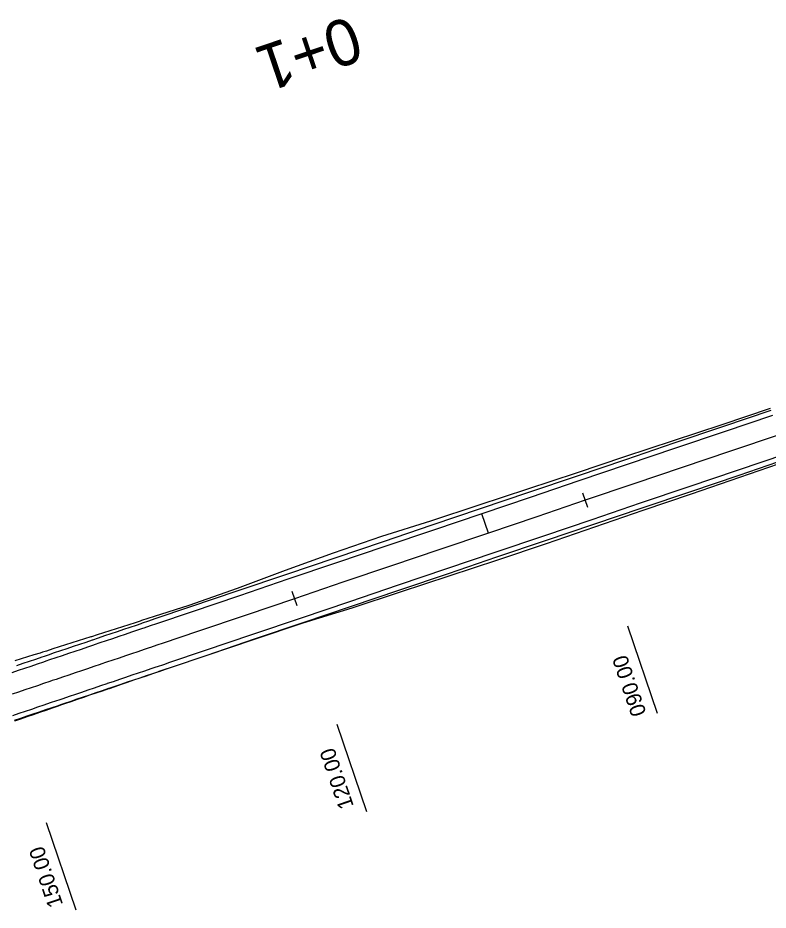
# Model space of a CAD drawing. Extents: x -550605 to -538780, y -1102367 to -1093705.
# Drawn here: x -546596.2 to -546522.8, y -1100741.3 to -1100654.1 of the extents above; entities that cross this region are included whole.
import ezdxf

# ---------------------------------------------------------------- set-up
doc = ezdxf.new("R2010")
doc.units = 0
for name, color, linetype in [('SIT - hrany vozovky', 7, 'Continuous'), ('SIT - osa cesty', 7, 'Continuous'), ('SIT - paty násypů', 7, 'Continuous'), ('SIT - staničení po 100m', 7, 'Continuous'), ('SIT - staničení po 30m', 7, 'Continuous')]:
    doc.layers.add(name, color=color, linetype=linetype)

msp = doc.modelspace()

# ---------------------------------------------------------------- linework, layer by layer
at = {"layer": 'SIT - hrany vozovky'}
for points in [[(-546522.558, -1100692.477), (-546527.294, -1100694.08), (-546532.03, -1100695.684), (-546536.766, -1100697.287), (-546541.502, -1100698.89), (-546546.238, -1100700.494), (-546550.974, -1100702.097), (-546555.709, -1100703.701), (-546560.445, -1100705.304), (-546565.181, -1100706.907), (-546569.917, -1100708.511), (-546574.653, -1100710.114), (-546579.389, -1100711.717), (-546582.768, -1100712.861), (-546583.382, -1100713.069), (-546583.997, -1100713.277), (-546584.125, -1100713.321), (-546584.611, -1100713.485), (-546585.225, -1100713.693), (-546585.84, -1100713.901), (-546586.454, -1100714.109), (-546587.069, -1100714.317), (-546587.683, -1100714.525), (-546588.298, -1100714.733), (-546588.861, -1100714.924), (-546588.912, -1100714.941), (-546589.526, -1100715.149), (-546590.141, -1100715.357), (-546590.755, -1100715.565), (-546591.37, -1100715.773), (-546591.984, -1100715.981), (-546592.598, -1100716.189), (-546593.213, -1100716.397), (-546593.597, -1100716.527), (-546593.827, -1100716.605), (-546594.442, -1100716.813), (-546595.056, -1100717.021), (-546595.67, -1100717.229), (-546596.285, -1100717.437)], [(-546522.397, -1100692.951), (-546527.133, -1100694.554), (-546531.869, -1100696.157), (-546536.605, -1100697.761), (-546541.341, -1100699.364), (-546546.077, -1100700.967), (-546550.813, -1100702.571), (-546555.549, -1100704.174), (-546560.285, -1100705.777), (-546565.021, -1100707.381), (-546569.757, -1100708.984), (-546574.493, -1100710.588), (-546579.229, -1100712.191), (-546582.607, -1100713.335), (-546583.222, -1100713.543), (-546583.836, -1100713.751), (-546583.965, -1100713.794), (-546584.451, -1100713.959), (-546585.065, -1100714.167), (-546585.68, -1100714.375), (-546586.294, -1100714.583), (-546586.908, -1100714.791), (-546587.523, -1100714.999), (-546588.137, -1100715.207), (-546588.701, -1100715.398), (-546588.752, -1100715.415), (-546589.366, -1100715.623), (-546589.98, -1100715.831), (-546590.595, -1100716.039), (-546591.209, -1100716.247), (-546591.824, -1100716.455), (-546592.438, -1100716.663), (-546593.052, -1100716.871), (-546593.437, -1100717.001), (-546593.667, -1100717.079), (-546594.281, -1100717.287), (-546594.896, -1100717.495), (-546595.51, -1100717.703), (-546596.125, -1100717.911), (-546596.739, -1100718.119)], [(-546521.115, -1100696.739), (-546525.851, -1100698.343), (-546530.587, -1100699.946), (-546535.323, -1100701.549), (-546540.059, -1100703.153), (-546544.795, -1100704.756), (-546549.53, -1100706.36), (-546554.266, -1100707.963), (-546559.002, -1100709.566), (-546563.738, -1100711.17), (-546568.474, -1100712.773), (-546573.21, -1100714.376), (-546577.946, -1100715.98), (-546581.325, -1100717.123), (-546581.939, -1100717.331), (-546582.554, -1100717.539), (-546582.682, -1100717.583), (-546583.168, -1100717.747), (-546583.782, -1100717.956), (-546584.397, -1100718.164), (-546585.011, -1100718.372), (-546585.626, -1100718.58), (-546586.24, -1100718.788), (-546586.854, -1100718.996), (-546587.418, -1100719.186), (-546587.469, -1100719.204), (-546588.083, -1100719.412), (-546588.698, -1100719.62), (-546589.312, -1100719.828), (-546589.927, -1100720.036), (-546590.541, -1100720.244), (-546591.155, -1100720.452), (-546591.77, -1100720.66), (-546592.154, -1100720.79), (-546592.384, -1100720.868), (-546592.999, -1100721.076), (-546593.613, -1100721.284), (-546594.227, -1100721.492), (-546594.842, -1100721.7), (-546595.456, -1100721.908), (-546596.071, -1100722.116), (-546596.685, -1100722.324)], [(-546520.954, -1100697.213), (-546525.69, -1100698.816), (-546530.426, -1100700.42), (-546535.162, -1100702.023), (-546539.898, -1100703.626), (-546544.634, -1100705.23), (-546549.37, -1100706.833), (-546554.106, -1100708.436), (-546558.842, -1100710.04), (-546563.578, -1100711.643), (-546568.314, -1100713.247), (-546573.05, -1100714.85), (-546577.786, -1100716.453), (-546581.164, -1100717.597), (-546581.779, -1100717.805), (-546582.393, -1100718.013), (-546582.522, -1100718.057), (-546583.008, -1100718.221), (-546583.622, -1100718.429), (-546584.236, -1100718.637), (-546584.851, -1100718.845), (-546585.465, -1100719.053), (-546586.08, -1100719.261), (-546586.694, -1100719.469), (-546587.258, -1100719.66), (-546587.309, -1100719.677), (-546587.923, -1100719.885), (-546588.537, -1100720.093), (-546589.152, -1100720.301), (-546589.766, -1100720.509), (-546590.381, -1100720.717), (-546590.995, -1100720.925), (-546591.609, -1100721.133), (-546591.994, -1100721.263), (-546592.224, -1100721.341), (-546592.838, -1100721.549), (-546593.453, -1100721.757), (-546594.067, -1100721.965), (-546594.682, -1100722.173), (-546595.296, -1100722.381), (-546595.91, -1100722.589), (-546596.525, -1100722.797)]]:
    msp.add_lwpolyline(points, dxfattribs=at)
at = {"layer": 'SIT - osa cesty'}
msp.add_lwpolyline([(-546521.756, -1100694.845), (-546526.492, -1100696.448), (-546531.228, -1100698.052), (-546535.964, -1100699.655), (-546540.7, -1100701.258), (-546545.436, -1100702.862), (-546550.172, -1100704.465), (-546554.908, -1100706.068), (-546559.644, -1100707.672), (-546564.38, -1100709.275), (-546569.116, -1100710.879), (-546573.852, -1100712.482), (-546578.588, -1100714.085), (-546581.966, -1100715.229), (-546582.581, -1100715.437), (-546583.195, -1100715.645), (-546583.323, -1100715.689), (-546583.809, -1100715.853), (-546584.424, -1100716.061), (-546585.038, -1100716.269), (-546585.653, -1100716.477), (-546586.267, -1100716.685), (-546586.881, -1100716.893), (-546587.496, -1100717.101), (-546588.059, -1100717.292), (-546588.11, -1100717.309), (-546588.725, -1100717.517), (-546589.339, -1100717.725), (-546589.953, -1100717.933), (-546590.568, -1100718.141), (-546591.182, -1100718.349), (-546591.797, -1100718.557), (-546592.411, -1100718.765), (-546592.795, -1100718.895), (-546593.026, -1100718.973), (-546593.64, -1100719.181), (-546594.254, -1100719.389), (-546594.869, -1100719.597), (-546595.483, -1100719.805), (-546596.098, -1100720.013), (-546596.712, -1100720.221)], dxfattribs=at)
at = {"layer": 'SIT - paty násypů'}
for points in [[(-546522.628, -1100692.271), (-546527.361, -1100693.882), (-546532.108, -1100695.452), (-546536.856, -1100697.021), (-546541.603, -1100698.591), (-546546.349, -1100700.165), (-546551.094, -1100701.741), (-546555.842, -1100703.31), (-546560.613, -1100704.808), (-546565.348, -1100706.416), (-546570.045, -1100708.132), (-546574.728, -1100709.892), (-546579.453, -1100711.529), (-546582.847, -1100712.628), (-546583.464, -1100712.827), (-546584.081, -1100713.027), (-546584.211, -1100713.068), (-546584.699, -1100713.226), (-546585.316, -1100713.425), (-546585.934, -1100713.624), (-546586.551, -1100713.822), (-546587.169, -1100714.021), (-546587.787, -1100714.219), (-546588.405, -1100714.417), (-546588.971, -1100714.598), (-546589.022, -1100714.615), (-546589.64, -1100714.812), (-546590.258, -1100715.01), (-546590.876, -1100715.207), (-546591.495, -1100715.404), (-546592.113, -1100715.601), (-546592.731, -1100715.797), (-546593.349, -1100715.994), (-546593.736, -1100716.117), (-546593.968, -1100716.19), (-546594.588, -1100716.38), (-546595.209, -1100716.571), (-546595.829, -1100716.761), (-546596.45, -1100716.951)], [(-546520.895, -1100697.389), (-546525.622, -1100699.019), (-546530.351, -1100700.643), (-546535.079, -1100702.268), (-546539.808, -1100703.892), (-546544.537, -1100705.517), (-546549.278, -1100707.105), (-546554.028, -1100708.667), (-546558.778, -1100710.23), (-546563.527, -1100711.793), (-546568.3, -1100713.288), (-546573.047, -1100714.857), (-546577.783, -1100716.463), (-546581.16, -1100717.609), (-546581.775, -1100717.817), (-546582.389, -1100718.026), (-546582.518, -1100718.069), (-546583.003, -1100718.234), (-546583.618, -1100718.443), (-546584.232, -1100718.651), (-546584.846, -1100718.86), (-546585.46, -1100719.07), (-546586.074, -1100719.279), (-546586.688, -1100719.489), (-546587.251, -1100719.681), (-546587.301, -1100719.698), (-546587.915, -1100719.908), (-546588.529, -1100720.118), (-546589.143, -1100720.329), (-546589.756, -1100720.539), (-546590.37, -1100720.75), (-546590.983, -1100720.96), (-546591.596, -1100721.171), (-546591.98, -1100721.304), (-546592.21, -1100721.383), (-546592.823, -1100721.594), (-546593.436, -1100721.806), (-546594.049, -1100722.017), (-546594.663, -1100722.229), (-546595.276, -1100722.441), (-546595.889, -1100722.654), (-546596.501, -1100722.866)]]:
    msp.add_lwpolyline(points, dxfattribs=at)
at = {"layer": 'SIT - staničení po 100m'}
msp.add_lwpolyline([(-546550.172, -1100704.465), (-546550.813, -1100702.571)], dxfattribs=at)
at = {"layer": 'SIT - staničení po 30m'}
for points in [[(-546540.459, -1100701.969), (-546540.94, -1100700.548)], [(-546568.875, -1100711.589), (-546569.356, -1100710.168)], [(-546533.645, -1100722.097), (-546536.531, -1100713.572)], [(-546562.061, -1100731.717), (-546564.947, -1100723.192)], [(-546590.477, -1100741.337), (-546593.363, -1100732.812)]]:
    msp.add_lwpolyline(points, dxfattribs=at)

# ---------------------------------------------------------------- texts
at = {"layer": 'SIT - staničení po 100m'}
msp.add_text('0+1', height=4.5, rotation=198.70354, dxfattribs=at).set_placement((-546563.554, -1100653.832))
at = {"layer": 'SIT - staničení po 30m'}
for s, p in [('090.00', (-546534.708, -1100722.077)), ('120.00', (-546563.305, -1100731.16)), ('150.00', (-546591.721, -1100740.78))]:
    msp.add_text(s, height=1.5, rotation=108.70354, dxfattribs=at).set_placement(p)

doc.saveas('drawing.dxf')
